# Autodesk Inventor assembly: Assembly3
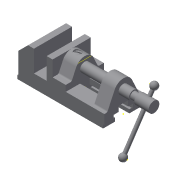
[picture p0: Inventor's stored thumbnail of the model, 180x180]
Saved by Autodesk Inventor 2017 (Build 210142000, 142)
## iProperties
Created: 2016-05
Part Number: Assembly3
Document SubType Name: Assembly
Designer: Sandeep
Author: Sandeep
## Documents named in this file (11)
- C:\Users\Sandeep\Desktop\New folder\joint tut\Assembly3.iam
- C:\Users\Sandeep\Desktop\New folder\joint tut\Base1.ipt
- C:\Users\Sandeep\Desktop\New folder\joint tut\base plate.ipt
- C:\Users\Sandeep\Desktop\New folder\joint tut\vice jaw.ipt
- C:\Users\Sandeep\Desktop\New folder\joint tut\jaw screw.ipt
- C:\Users\Sandeep\Desktop\New folder\joint tut\clamping plate.ipt
- C:\Users\Sandeep\Desktop\New folder\joint tut\Screw Bar.ipt
- C:\Users\Sandeep\Desktop\New folder\joint tut\bar globes.ipt
- C:\Users\Sandeep\Desktop\New folder\joint tut\set scew 1.ipt
- C:\Users\Sandeep\Desktop\New folder\joint tut\set scew 2.ipt
- C:\Users\Sandeep\Desktop\New folder\joint tut\Oval Filister.ipt
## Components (15 placed, 10 different names)
1. Base1:1 — Insert:3, Insert:4, Slider:1, Cylindrical:1, Insert:7, Insert:8, Mate:3, Mate:5
2. base plate:1 — Insert:7, Insert:8, Mate:6, Mate:7
3. base plate:2 — Insert:3, Insert:4
4. vice jaw:1 — Slider:1, Mate:1, Insert:9, Mate:2, Mate:8, Mate:10, Mate:12, Mate:13, Mate:14
5. jaw screw:1 — Cylindrical:1, Mate:1, Cylindrical:2
6. clamping plate:1 — Insert:9, Mate:2, Mate:9, Mate:11
7. Screw Bar:1 — Cylindrical:2, Rigid:2, Rigid:3
8. bar globes:1 — Rigid:2
9. bar globes:2 — Rigid:3
10. set scew 1:2 — Mate:3
11. set scew 1:3 — Mate:5
12. set scew 1:4 — Mate:6, Mate:7
13. set scew 2:1 — Mate:8, Mate:9
14. set scew 2:2 — Mate:10, Mate:11
15. Oval Filister:1 — Mate:12, Mate:13, Mate:14
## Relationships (23: Mate 13, Insert 5, CylindricalJoint 2, WeldJoint 2, TranslationJoint 1)
- Insert:3: Base1:1 ↔ base plate:2
- Insert:4: Base1:1 ↔ base plate:2
- Slider:1 [TranslationJoint]: Base1:1 ↔ vice jaw:1
- Cylindrical:1: Base1:1 ↔ jaw screw:1
- Mate:1: vice jaw:1 ↔ jaw screw:1
- Insert:7: Base1:1 ↔ base plate:1
- Insert:8: Base1:1 ↔ base plate:1
- Cylindrical:2: jaw screw:1 ↔ Screw Bar:1
- Rigid:2 [WeldJoint]: Screw Bar:1 ↔ bar globes:1
- Rigid:3 [WeldJoint]: Screw Bar:1 ↔ bar globes:2
- Insert:9: vice jaw:1 ↔ clamping plate:1
- Mate:2: vice jaw:1 ↔ clamping plate:1
- Mate:3: Base1:1 ↔ set scew 1:2
- Mate:5: Base1:1 ↔ set scew 1:3
- Mate:6: base plate:1 ↔ set scew 1:4
- Mate:7: base plate:1 ↔ set scew 1:4
- Mate:8: vice jaw:1 ↔ set scew 2:1
- Mate:9: clamping plate:1 ↔ set scew 2:1
- Mate:10: vice jaw:1 ↔ set scew 2:2
- Mate:11: clamping plate:1 ↔ set scew 2:2
- Mate:12: vice jaw:1 ↔ Oval Filister:1
- Mate:13: vice jaw:1 ↔ Oval Filister:1
- Mate:14: vice jaw:1 ↔ Oval Filister:1
